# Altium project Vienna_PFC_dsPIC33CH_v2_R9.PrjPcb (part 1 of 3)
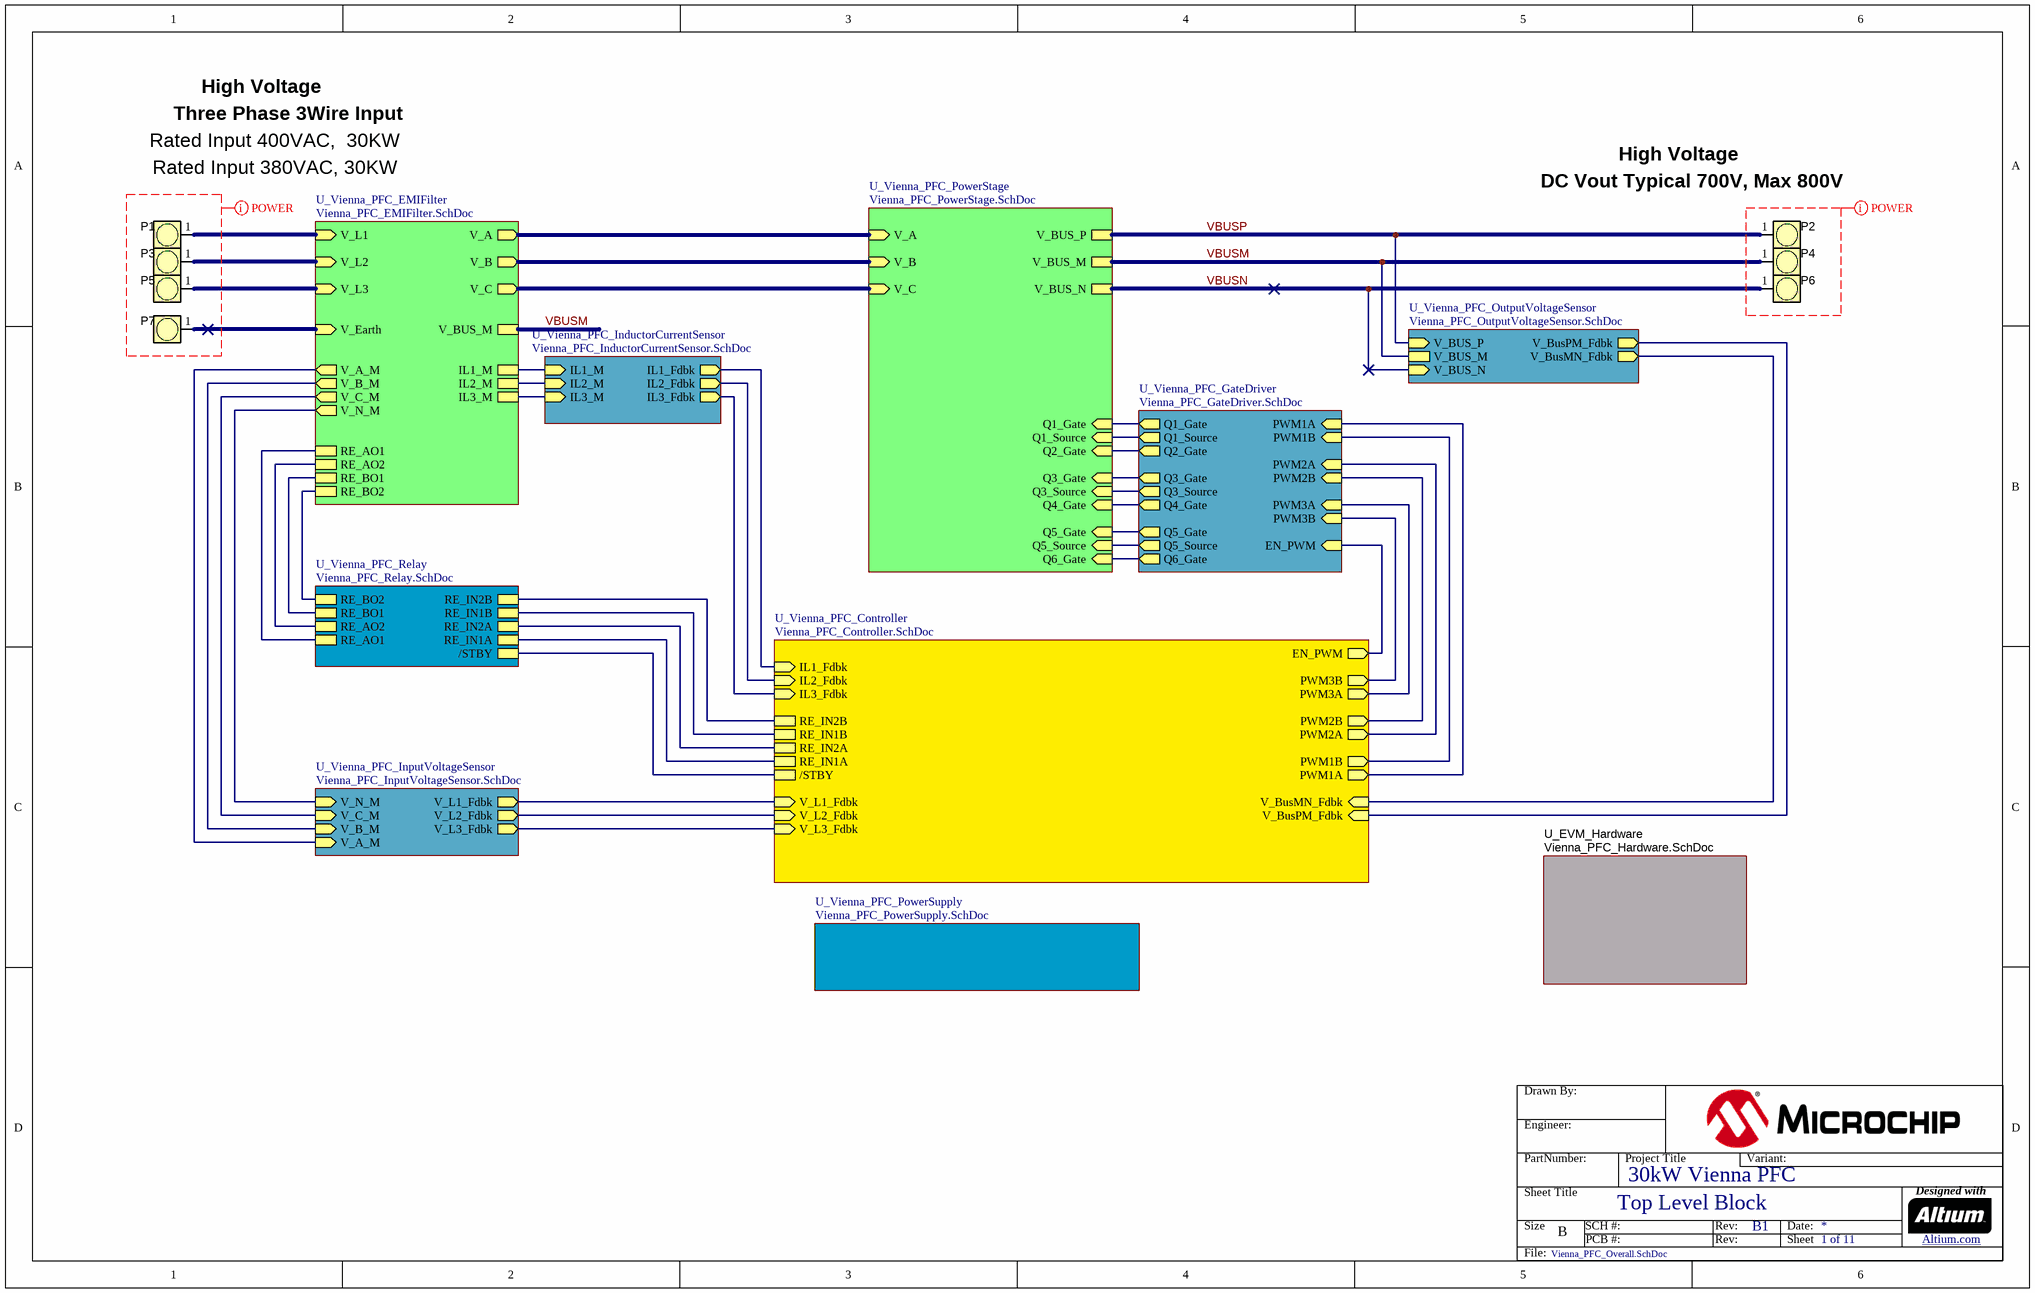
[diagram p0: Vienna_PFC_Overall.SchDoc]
11 sheets, 641 parts. Net scope: hierarchical (ports join the sheet entries above them; power ports are global).
Board file: Vienna_PFC_PCB.PcbDoc
Sheets:
  Vienna_PFC_Overall.SchDoc
    U_EVM_Hardware = Vienna_PFC_Hardware.SchDoc
    U_Vienna_PFC_InputVoltageSensor = Vienna_PFC_InputVoltageSensor.SchDoc
    U_Vienna_PFC_PowerStage = Vienna_PFC_PowerStage.SchDoc
    U_Vienna_PFC_GateDriver = Vienna_PFC_GateDriver.SchDoc
    U_Vienna_PFC_OutputVoltageSensor = Vienna_PFC_OutputVoltageSensor.SchDoc
    U_Vienna_PFC_InductorCurrentSensor = Vienna_PFC_InductorCurrentSensor.SchDoc
    U_Vienna_PFC_PowerSupply = Vienna_PFC_PowerSupply.SchDoc
    U_Vienna_PFC_EMIFilter = Vienna_PFC_EMIFilter.SchDoc
    U_Vienna_PFC_Relay = Vienna_PFC_Relay.SchDoc
    U_Vienna_PFC_Controller = Vienna_PFC_Controller.SchDoc

## Sheet Vienna_PFC_Overall.SchDoc
size B; DocumentNumber: 1; SheetNumber: 1; SheetTotal: 11

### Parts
(Parts that share a designator on the sheet are numbered #1, #2 ... from top to bottom, then left to right.)
?#1  (no value)  (graphical)
P1  Bush_7460408  [Bush7460408]  (value not drawn)
P2  Bush_7460408  [Bush7460408]  (value not drawn)
P3  Bush_7460408  [Bush7460408]  (value not drawn)
P4  Bush_7460408  [Bush7460408]  (value not drawn)
P5  Bush_7460408  [Bush7460408]  (value not drawn)
P6  Bush_7460408  [Bush7460408]  (value not drawn)
P7  Bush_7460408  [Bush7460408]  (value not drawn)

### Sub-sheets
U_EVM_Hardware = Vienna_PFC_Hardware.SchDoc: no entries
U_Vienna_PFC_Controller = Vienna_PFC_Controller.SchDoc: V_L3_Fdbk (in), PWM2A (out), PWM2B (out), IL1_Fdbk (in), IL2_Fdbk (in), IL3_Fdbk (in), V_L1_Fdbk (in), V_L2_Fdbk (in), V_BusPM_Fdbk (in), V_BusMN_Fdbk (in), EN_PWM (out), PWM3B (out), PWM1B (out), PWM3A (out), PWM1A (out), RE_IN2A, RE_IN1A, RE_IN2B, RE_IN1B, /STBY
U_Vienna_PFC_EMIFilter = Vienna_PFC_EMIFilter.SchDoc: RE_AO2, RE_BO2, V_L1 (in), V_L2 (in), V_L3 (in), V_Earth (in), V_A_M (out), V_B_M (out), V_C_M (out), V_BUS_M, V_N_M (out), IL1_M, IL2_M, IL3_M, V_A (out), V_C (out), V_B (out), RE_AO1, RE_BO1
U_Vienna_PFC_GateDriver = Vienna_PFC_GateDriver.SchDoc: PWM1A (in), PWM1B (in), PWM2A (in), PWM2B (in), PWM3A (in), PWM3B (in), Q1_Source (out), Q3_Source (out), Q5_Source (out), EN_PWM (in), Q1_Gate (out), Q3_Gate (out), Q5_Gate (out), Q2_Gate (out), Q4_Gate (out), Q6_Gate (out)
U_Vienna_PFC_InductorCurrentSensor = Vienna_PFC_InductorCurrentSensor.SchDoc: IL1_M (in), IL2_M (in), IL3_M (in), IL1_Fdbk (out), IL2_Fdbk (out), IL3_Fdbk (out)
U_Vienna_PFC_InputVoltageSensor = Vienna_PFC_InputVoltageSensor.SchDoc: V_A_M (in), V_B_M (in), V_C_M (in), V_N_M (in), V_L1_Fdbk (out), V_L2_Fdbk (out), V_L3_Fdbk (out)
U_Vienna_PFC_OutputVoltageSensor = Vienna_PFC_OutputVoltageSensor.SchDoc: V_BUS_P (in), V_BUS_N (in), V_BusPM_Fdbk (out), V_BusMN_Fdbk (out), V_BUS_M
U_Vienna_PFC_PowerStage = Vienna_PFC_PowerStage.SchDoc: V_A (in), V_B (in), V_C (in), Q1_Source (in), Q2_Gate (in), Q3_Source (in), Q5_Source (in), Q3_Gate (in), Q4_Gate (in), Q6_Gate (in), Q5_Gate (in), Q1_Gate (in), V_BUS_P, V_BUS_M, V_BUS_N
U_Vienna_PFC_PowerSupply = Vienna_PFC_PowerSupply.SchDoc: no entries
U_Vienna_PFC_Relay = Vienna_PFC_Relay.SchDoc: RE_AO1, RE_AO2, RE_BO1, RE_BO2, RE_IN2A, RE_IN1A, RE_IN2B, RE_IN1B, /STBY

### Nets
GND1: sheet U_Vienna_PFC_PowerStage/Q1_Source, sheet U_Vienna_PFC_GateDriver/Q1_Source
GND3: sheet U_Vienna_PFC_PowerStage/Q3_Source, sheet U_Vienna_PFC_GateDriver/Q3_Source
GND5: sheet U_Vienna_PFC_PowerStage/Q5_Source, sheet U_Vienna_PFC_GateDriver/Q5_Source
PE: P7.1 ; sheet U_Vienna_PFC_EMIFilter/V_Earth
EN_PWM: sheet U_Vienna_PFC_GateDriver/EN_PWM, sheet U_Vienna_PFC_Controller/EN_PWM
V_N_Meas: sheet U_Vienna_PFC_InputVoltageSensor/V_N_M, sheet U_Vienna_PFC_EMIFilter/V_N_M
VBUSM: P4.1 ; sheet U_Vienna_PFC_PowerStage/V_BUS_M, sheet U_Vienna_PFC_OutputVoltageSensor/V_BUS_M, sheet U_Vienna_PFC_EMIFilter/V_BUS_M  [project net V_BUS_M]
VBUSN: P6.1 ; sheet U_Vienna_PFC_PowerStage/V_BUS_N, sheet U_Vienna_PFC_OutputVoltageSensor/V_BUS_N
VBUSP: P2.1 ; sheet U_Vienna_PFC_PowerStage/V_BUS_P, sheet U_Vienna_PFC_OutputVoltageSensor/V_BUS_P
NetC14_2: sheet U_Vienna_PFC_InputVoltageSensor/V_C_M, sheet U_Vienna_PFC_EMIFilter/V_C_M
NetC15_2: sheet U_Vienna_PFC_InputVoltageSensor/V_B_M, sheet U_Vienna_PFC_EMIFilter/V_B_M
NetC16_2: sheet U_Vienna_PFC_InputVoltageSensor/V_A_M, sheet U_Vienna_PFC_EMIFilter/V_A_M
NetC110_1: sheet U_Vienna_PFC_InductorCurrentSensor/IL1_Fdbk, sheet U_Vienna_PFC_Controller/IL1_Fdbk
NetC112_1: sheet U_Vienna_PFC_InductorCurrentSensor/IL2_Fdbk, sheet U_Vienna_PFC_Controller/IL2_Fdbk
NetC114_1: sheet U_Vienna_PFC_InductorCurrentSensor/IL3_Fdbk, sheet U_Vienna_PFC_Controller/IL3_Fdbk
NetC122_2: sheet U_Vienna_PFC_InputVoltageSensor/V_L1_Fdbk, sheet U_Vienna_PFC_Controller/V_L1_Fdbk
NetC139_2: sheet U_Vienna_PFC_InputVoltageSensor/V_L2_Fdbk, sheet U_Vienna_PFC_Controller/V_L2_Fdbk
NetC149_2: sheet U_Vienna_PFC_InputVoltageSensor/V_L3_Fdbk, sheet U_Vienna_PFC_Controller/V_L3_Fdbk
NetC159_2: sheet U_Vienna_PFC_OutputVoltageSensor/V_BusPM_Fdbk, sheet U_Vienna_PFC_Controller/V_BusPM_Fdbk
NetC168_2: sheet U_Vienna_PFC_OutputVoltageSensor/V_BusMN_Fdbk, sheet U_Vienna_PFC_Controller/V_BusMN_Fdbk
NetJ5_13: sheet U_Vienna_PFC_Relay/RE_IN1B, sheet U_Vienna_PFC_Controller/RE_IN1B
NetJ5_15: sheet U_Vienna_PFC_Relay/RE_IN2B, sheet U_Vienna_PFC_Controller/RE_IN2B
NetJ5_31: sheet U_Vienna_PFC_Relay//STBY, sheet U_Vienna_PFC_Controller//STBY
NetJ5_33: sheet U_Vienna_PFC_Relay/RE_IN1A, sheet U_Vienna_PFC_Controller/RE_IN1A
NetJ5_35: sheet U_Vienna_PFC_Relay/RE_IN2A, sheet U_Vienna_PFC_Controller/RE_IN2A
NetJ5_37: sheet U_Vienna_PFC_GateDriver/PWM3A, sheet U_Vienna_PFC_Controller/PWM3A
NetJ5_40: sheet U_Vienna_PFC_GateDriver/PWM2B, sheet U_Vienna_PFC_Controller/PWM2B
NetJ5_41: sheet U_Vienna_PFC_GateDriver/PWM3B, sheet U_Vienna_PFC_Controller/PWM3B
NetJ5_42: sheet U_Vienna_PFC_GateDriver/PWM2A, sheet U_Vienna_PFC_Controller/PWM2A
NetJ5_45: sheet U_Vienna_PFC_GateDriver/PWM1A, sheet U_Vienna_PFC_Controller/PWM1A
NetJ5_47: sheet U_Vienna_PFC_GateDriver/PWM1B, sheet U_Vienna_PFC_Controller/PWM1B
NetLboost1_1: sheet U_Vienna_PFC_PowerStage/V_A, sheet U_Vienna_PFC_EMIFilter/V_A
NetLboost2_1: sheet U_Vienna_PFC_PowerStage/V_B, sheet U_Vienna_PFC_EMIFilter/V_B
NetLboost3_1: sheet U_Vienna_PFC_PowerStage/V_C, sheet U_Vienna_PFC_EMIFilter/V_C
NetP1_1: P1.1 ; sheet U_Vienna_PFC_EMIFilter/V_L1
NetP3_1: P3.1 ; sheet U_Vienna_PFC_EMIFilter/V_L2
NetP5_1: P5.1 ; sheet U_Vienna_PFC_EMIFilter/V_L3
NetR11_2: sheet U_Vienna_PFC_PowerStage/Q2_Gate, sheet U_Vienna_PFC_GateDriver/Q2_Gate
NetR12_2: sheet U_Vienna_PFC_PowerStage/Q1_Gate, sheet U_Vienna_PFC_GateDriver/Q1_Gate
NetR28_2: sheet U_Vienna_PFC_PowerStage/Q4_Gate, sheet U_Vienna_PFC_GateDriver/Q4_Gate
NetR29_2: sheet U_Vienna_PFC_PowerStage/Q3_Gate, sheet U_Vienna_PFC_GateDriver/Q3_Gate
NetR44_2: sheet U_Vienna_PFC_PowerStage/Q6_Gate, sheet U_Vienna_PFC_GateDriver/Q6_Gate
NetR45_2: sheet U_Vienna_PFC_PowerStage/Q5_Gate, sheet U_Vienna_PFC_GateDriver/Q5_Gate
NetR171_2: sheet U_Vienna_PFC_InductorCurrentSensor/IL1_M, sheet U_Vienna_PFC_EMIFilter/IL1_M
NetR174_2: sheet U_Vienna_PFC_InductorCurrentSensor/IL2_M, sheet U_Vienna_PFC_EMIFilter/IL2_M
NetR177_2: sheet U_Vienna_PFC_InductorCurrentSensor/IL3_M, sheet U_Vienna_PFC_EMIFilter/IL3_M
NetR180_2: sheet U_Vienna_PFC_EMIFilter/RE_AO1, sheet U_Vienna_PFC_Relay/RE_AO1
NetR181_2: sheet U_Vienna_PFC_EMIFilter/RE_AO2, sheet U_Vienna_PFC_Relay/RE_AO2
NetR182_2: sheet U_Vienna_PFC_EMIFilter/RE_BO1, sheet U_Vienna_PFC_Relay/RE_BO1
NetR183_2: sheet U_Vienna_PFC_EMIFilter/RE_BO2, sheet U_Vienna_PFC_Relay/RE_BO2

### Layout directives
net class POWER: (no net found under the mark)

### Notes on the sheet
- High Voltage
- Rated Input 400VAC,  30KW
- Rated Input 380VAC, 30KW
- Three Phase 3Wire Input
- (near P2) DC Vout Typical 700V, Max 800V
- Top Level Block
- 30kW Vienna PFC
- B1

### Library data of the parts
?#1 = Title Block B
P1-P7 = Bush_7460408: TERM PWR ELEMENT M5 12 PIN PCB; Manufacturer: Wurth Electronics Inc.

## Sheet Vienna_PFC_Hardware.SchDoc: EVM Hardware
size B; Date: Not shown in title block; ApprovedBy: Not shown in title block; CheckedBy: Not shown in title block; Author: Not shown in title block; CompanyName: Not shown in title block; DrawnBy: SJC; Engineer: SJC; Organization: Not shown in title block; Address1: Not shown in title block; Address2: Not shown in title block; Address3: Not shown in title block; Address4: Not shown in title block; DocumentNumber: 11; Revision: B1; SheetNumber: 11; SheetTotal: 11; PageSetup: Record=PageOptions¦CenterHorizontal=True¦CenterVertical=True¦PrintScale=1.00¦XCorrection=1.00¦YCorrection=1.00¦PrintKind=0¦BorderSize=5000000¦LeftOffset=0¦BottomOffset=0¦Orientation=2¦PaperLength=1000¦PaperWidth=1000¦Scale=100¦PaperSource=15¦PrintQuality=600¦MediaType=1¦DitherType=10¦PaperKind=Letter¦PrintScaleMode=1; SheetTitle: **
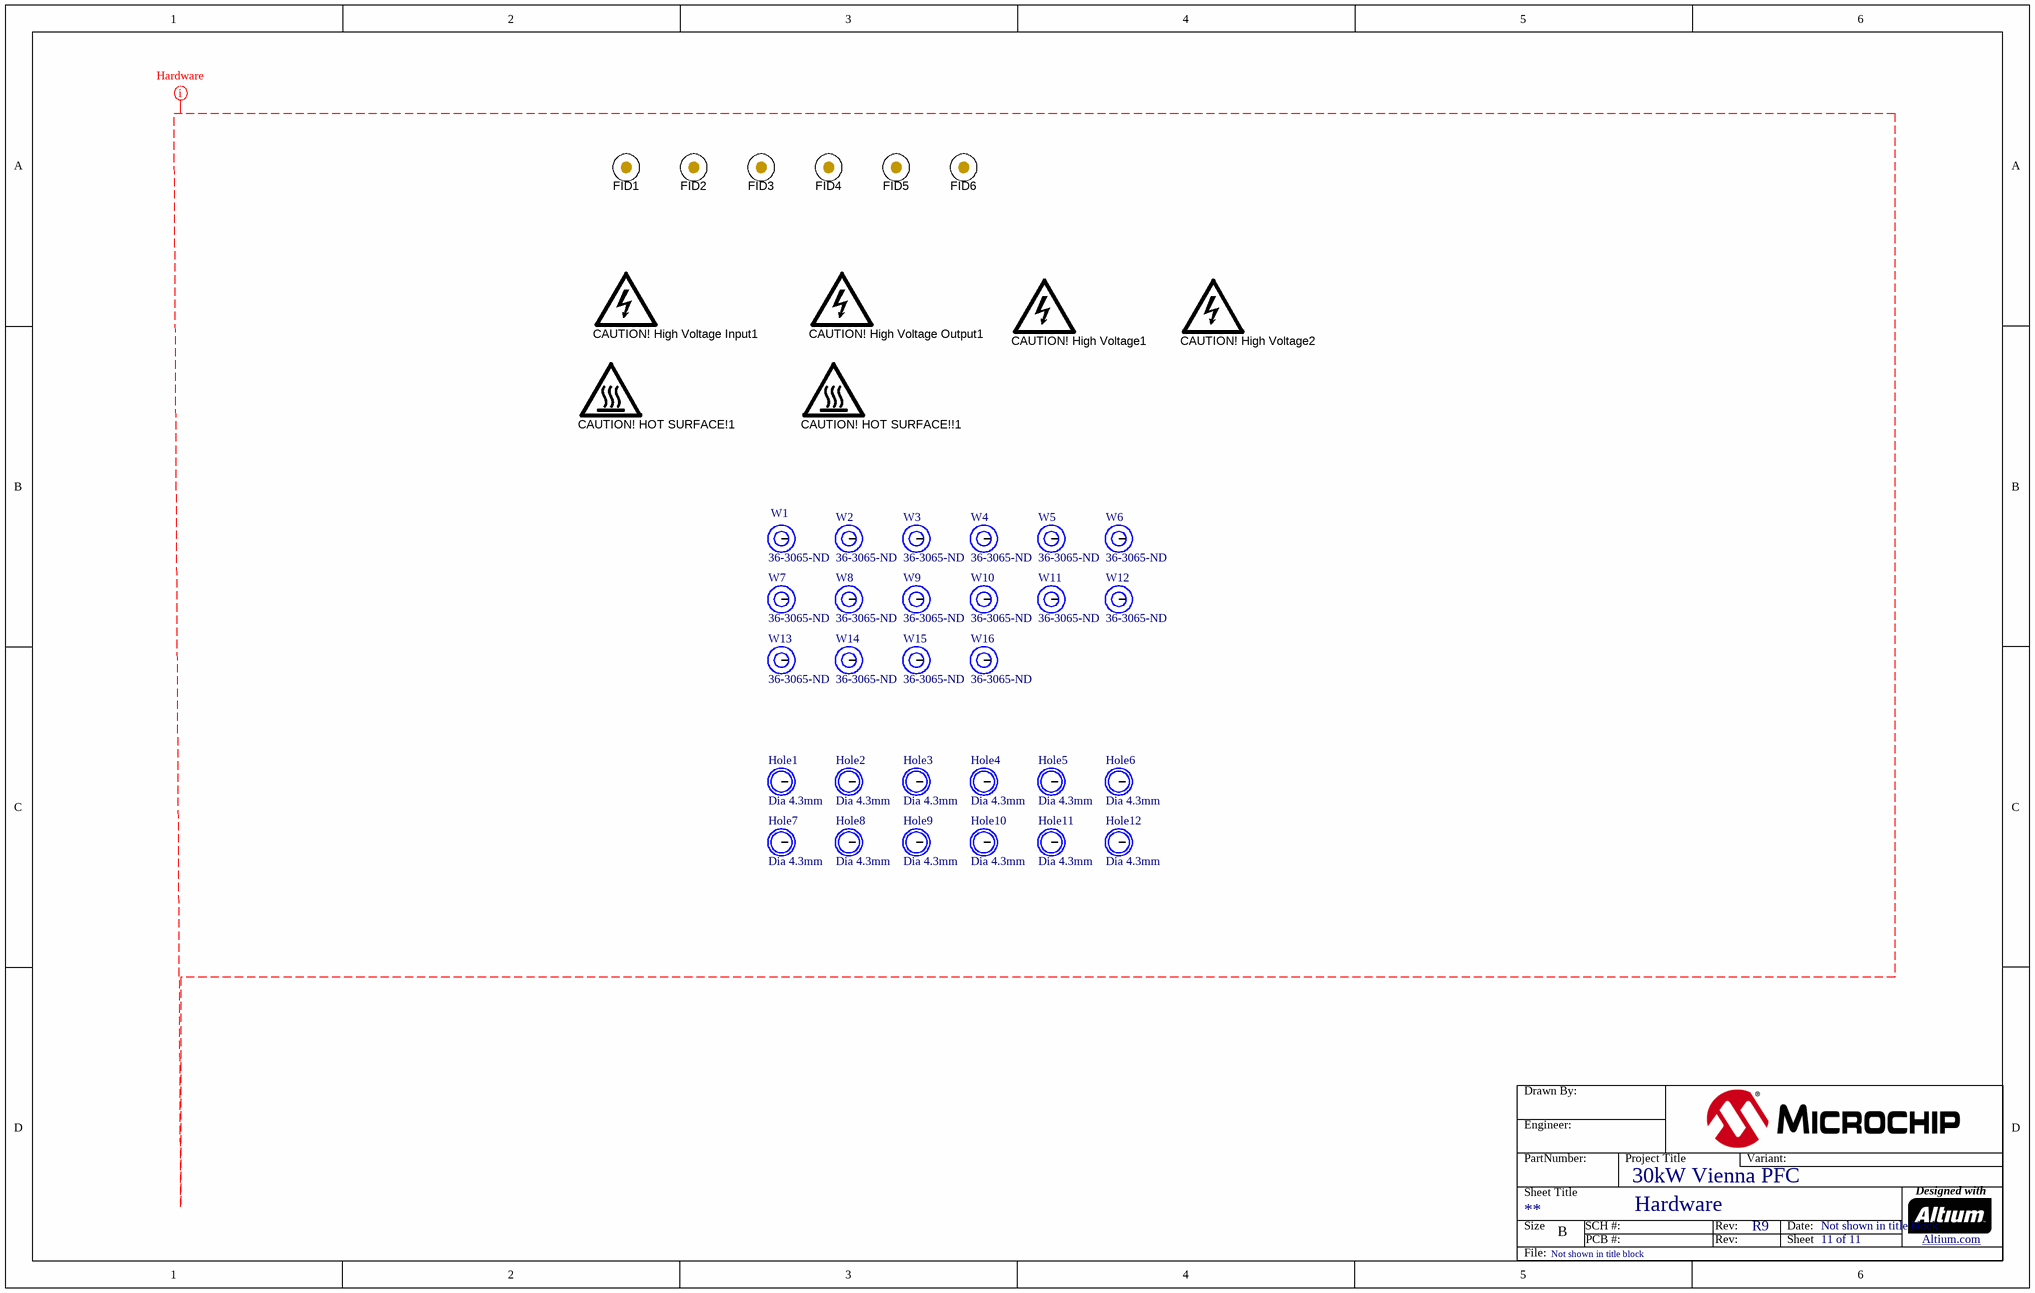
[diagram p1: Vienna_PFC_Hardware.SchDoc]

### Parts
(Parts that share a designator on the sheet are numbered #1, #2 ... from top to bottom, then left to right.)
?#2  (no value)  (graphical)
CAUTION!_High_Voltage1  DANGER HIGH VOLTAGE  [IEC_HighVoltage_Small]  (value not drawn)  (no BOM)
CAUTION!_High_Voltage2  DANGER HIGH VOLTAGE  [IEC_HighVoltage_Small]  (value not drawn)  (no BOM)
CAUTION!_High_Voltage_Input1  DANGER HIGH VOLTAGE  [IEC_HighVoltage_Small]  (value not drawn)  (no BOM)
CAUTION!_High_Voltage_Output1  DANGER HIGH VOLTAGE  [IEC_HighVoltage_Small]  (value not drawn)  (no BOM)
CAUTION!_HOT_SURFACE!1  CAUTION HOT SURFACE  [IEC_HotSurface_Small]  (value not drawn)  (no BOM)
CAUTION!_HOT_SURFACE!!1  CAUTION HOT SURFACE  [IEC_HotSurface_Small]  (value not drawn)  (no BOM)
FID1  Fiducial  [Fiducial10-20]  (value not drawn)  (no BOM)
FID2  Fiducial  [Fiducial10-20]  (value not drawn)
FID3  Fiducial  [Fiducial10-20]  (value not drawn)
FID4  Fiducial  [Fiducial10-20]  (value not drawn)  (no BOM)
FID5  Fiducial  [Fiducial10-20]  (value not drawn)
FID6  Fiducial  [Fiducial10-20]  (value not drawn)
Hole1  Dia 4.3mm  [Hole-Dia 4.3mm]
Hole2  Dia 4.3mm  [Hole-Dia 4.3mm]
Hole3  Dia 4.3mm  [Hole-Dia 4.3mm]
Hole4  Dia 4.3mm  [Hole-Dia 4.3mm]
Hole5  Dia 4.3mm  [Hole-Dia 4.3mm]
Hole6  Dia 4.3mm  [Hole-Dia 4.3mm]
Hole7  Dia 4.3mm  [Hole-Dia 4.3mm]
Hole8  Dia 4.3mm  [Hole-Dia 4.3mm]
Hole9  Dia 4.3mm  [Hole-Dia 4.3mm]
Hole10  Dia 4.3mm  [Hole-Dia 4.3mm]
Hole11  Dia 4.3mm  [Hole-Dia 4.3mm]
Hole12  Dia 4.3mm  [Hole-Dia 4.3mm]
W1  36-3065-ND  [WASHER SHOULDER]
W2  36-3065-ND  [WASHER SHOULDER]
W3  36-3065-ND  [WASHER SHOULDER]
W4  36-3065-ND  [WASHER SHOULDER]
W5  36-3065-ND  [WASHER SHOULDER]
W6  36-3065-ND  [WASHER SHOULDER]
W7  36-3065-ND  [WASHER SHOULDER]
W8  36-3065-ND  [WASHER SHOULDER]
W9  36-3065-ND  [WASHER SHOULDER]
W10  36-3065-ND  [WASHER SHOULDER]
W11  36-3065-ND  [WASHER SHOULDER]
W12  36-3065-ND  [WASHER SHOULDER]
W13  36-3065-ND  [WASHER SHOULDER]
W14  36-3065-ND  [WASHER SHOULDER]
W15  36-3065-ND  [WASHER SHOULDER]
W16  36-3065-ND  [WASHER SHOULDER]

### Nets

Not connected (* = marked no-connect by the designer): Hole1 0; Hole2 0; Hole3 0; Hole4 0; Hole5 0; Hole6 0; Hole7 0; Hole8 0; Hole9 0; Hole10 0; Hole11 0; Hole12 0; W1 0; W2 0; W3 0; W4 0; W5 0; W6 0; W7 0; W8 0; W9 0; W10 0; W11 0; W12 0; W13 0; W14 0; W15 0; W16 0

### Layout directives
net class Hardware: (no net found under the mark)

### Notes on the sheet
- 30kW Vienna PFC
- Hardware
- R9

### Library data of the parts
?#2 = Title Block B
CAUTION!_High_Voltage1 CAUTION!_High_Voltage2 CAUTION!_High_Voltage_Input1 CAUTION!_High_Voltage_Output1 = IEC_HighVoltage: IEC 61010-1 High Voltage Warning; SymbolCreator: a0412235
CAUTION!_HOT_SURFACE!1 CAUTION!_HOT_SURFACE!!1 = IEC_HotSurface: IEC 61010-1 Hot Surface Warning; SymbolCreator: a0412235
FID1-FID6 = Fiducial: Fiducial mark.  There is nothing to buy or mount.; SymbolCreator: codlsc
Hole1-Hole12 = Hole: Hole  Dia 4.3mm
W1-W16 = WASHER SHOULDER - 3065: WASHER SHOULDER #8 FIBRE

## Sheet Vienna_PFC_InputVoltageSensor.SchDoc
size C; DocumentNumber: 6; SheetNumber: 6; SheetTotal: 11
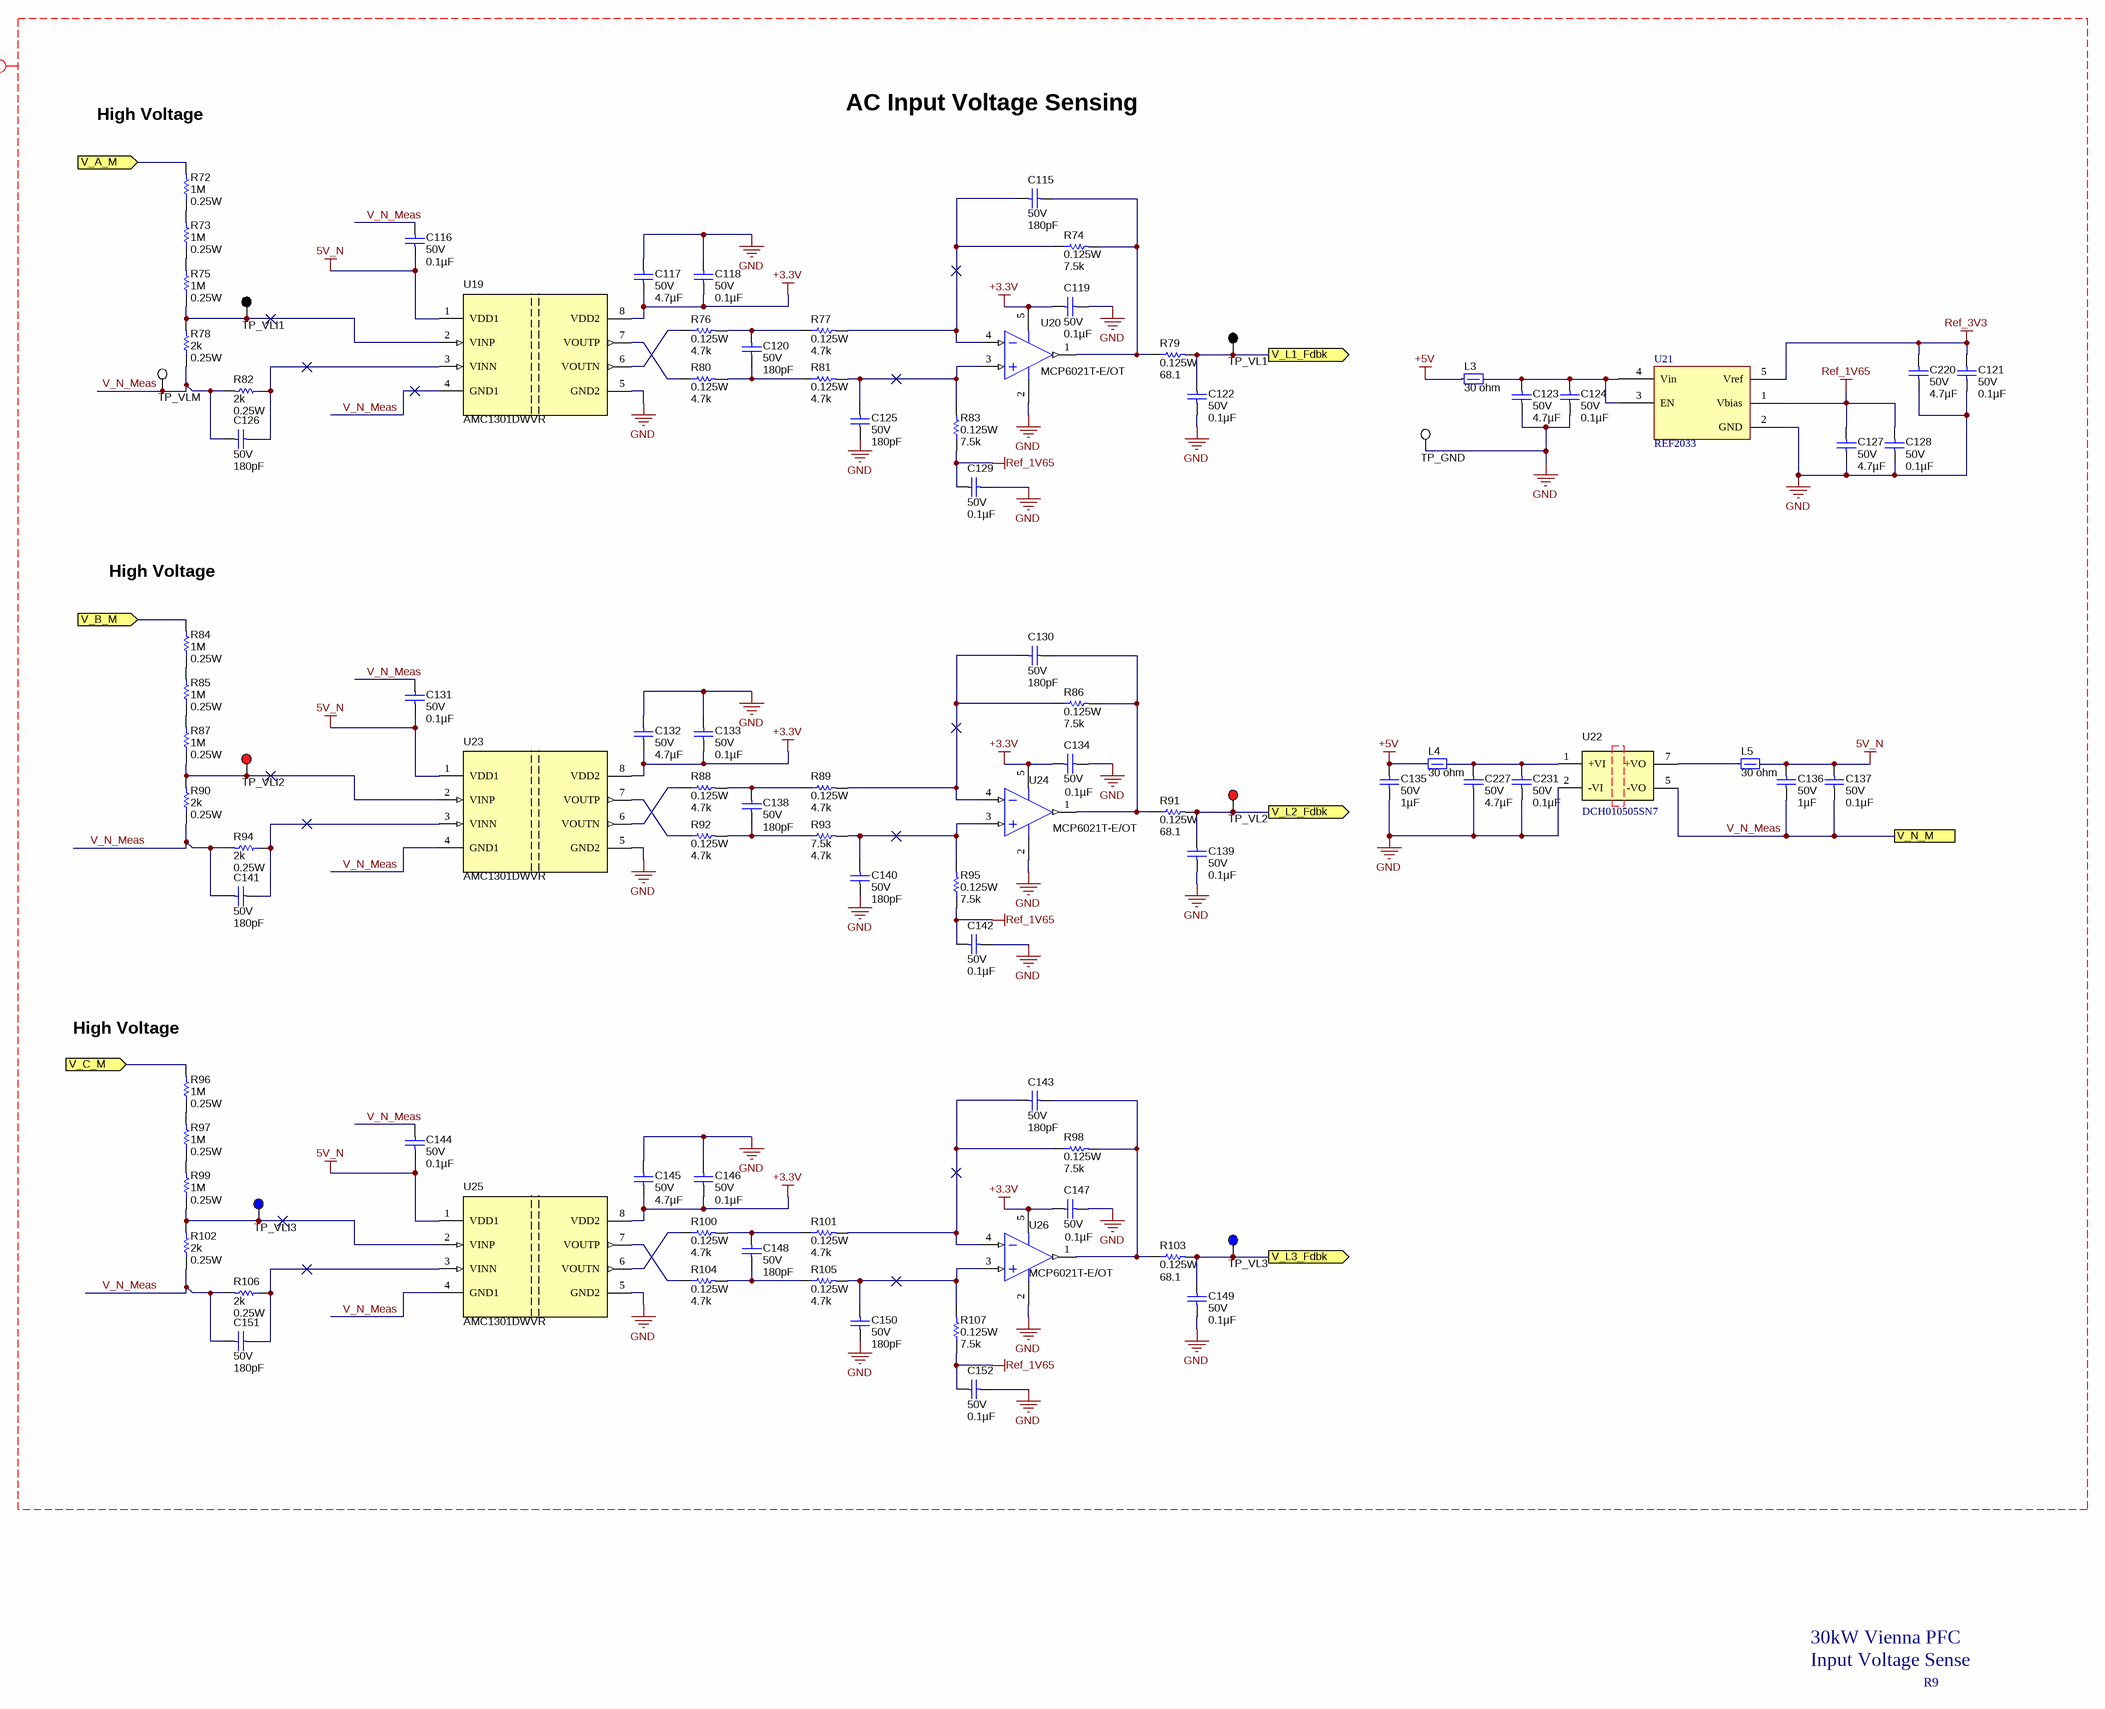
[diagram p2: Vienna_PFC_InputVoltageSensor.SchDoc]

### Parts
(Parts that share a designator on the sheet are numbered #1, #2 ... from top to bottom, then left to right.)
?#3  (no value)  (graphical)
C115  VDC_V: 50V  ValueDisplayed: 180pF  [0805_HV]  (hidden comment: C0805C181J5GACTU)
C116  VDC_V: 50V  ValueDisplayed: 0.1µF  [0805_HV]  (hidden comment: C0805C104J5RACTU)
C117  VDC_V: 50V  ValueDisplayed: 4.7µF  [0805_HV]  (hidden comment: C2012X5R1H475K125AB)
C118  VDC_V: 50V  ValueDisplayed: 0.1µF  [0805_HV]  (hidden comment: C0805C104J5RACTU)
C119  VDC_V: 50V  ValueDisplayed: 0.1µF  [0805_HV]  (hidden comment: C0805C104J5RACTU)
C120  VDC_V: 50V  ValueDisplayed: 180pF  [0805_HV]  (hidden comment: C0805C181J5GACTU)
C121  VDC_V: 50V  ValueDisplayed: 0.1µF  [0805_HV]  (hidden comment: C0805C104J5RACTU)
C122  VDC_V: 50V  ValueDisplayed: 0.1µF  [0805_HV]  (hidden comment: C0805C104J5RACTU)
C123  VDC_V: 50V  ValueDisplayed: 4.7µF  [0805_HV]  (hidden comment: C2012X5R1H475K125AB)
C124  VDC_V: 50V  ValueDisplayed: 0.1µF  [0805_HV]  (hidden comment: C0805C104J5RACTU)
C125  VDC_V: 50V  ValueDisplayed: 180pF  [0805_HV]  (hidden comment: C0805C181J5GACTU)
C126  VDC_V: 50V  ValueDisplayed: 180pF  [0805_HV]  (hidden comment: C0805C181J5GACTU)
C127  VDC_V: 50V  ValueDisplayed: 4.7µF  [0805_HV]  (hidden comment: C2012X5R1H475K125AB)
C128  VDC_V: 50V  ValueDisplayed: 0.1µF  [0805_HV]  (hidden comment: C0805C104J5RACTU)
C129  VDC_V: 50V  ValueDisplayed: 0.1µF  [0805_HV]  (hidden comment: C0805C104J5RACTU)
C130  VDC_V: 50V  ValueDisplayed: 180pF  [0805_HV]  (hidden comment: C0805C181J5GACTU)
C131  VDC_V: 50V  ValueDisplayed: 0.1µF  [0805_HV]  (hidden comment: C0805C104J5RACTU)
C132  VDC_V: 50V  ValueDisplayed: 4.7µF  [0805_HV]  (hidden comment: C2012X5R1H475K125AB)
C133  VDC_V: 50V  ValueDisplayed: 0.1µF  [0805_HV]  (hidden comment: C0805C104J5RACTU)
C134  VDC_V: 50V  ValueDisplayed: 0.1µF  [0805_HV]  (hidden comment: C0805C104J5RACTU)
C135  VDC_V: 50V  ValueDisplayed: 1µF  [0805_HV]  (hidden comment: C0805C105K5RACTU)
C136  VDC_V: 50V  ValueDisplayed: 1µF  [0805_HV]  (hidden comment: C0805C105K5RACTU)
C137  VDC_V: 50V  ValueDisplayed: 0.1µF  [0805_HV]  (hidden comment: C0805C104J5RACTU)
C138  VDC_V: 50V  ValueDisplayed: 180pF  [0805_HV]  (hidden comment: C0805C181J5GACTU)
C139  VDC_V: 50V  ValueDisplayed: 0.1µF  [0805_HV]  (hidden comment: C0805C104J5RACTU)
C140  VDC_V: 50V  ValueDisplayed: 180pF  [0805_HV]  (hidden comment: C0805C181J5GACTU)
C141  VDC_V: 50V  ValueDisplayed: 180pF  [0805_HV]  (hidden comment: C0805C181J5GACTU)
C142  VDC_V: 50V  ValueDisplayed: 0.1µF  [0805_HV]  (hidden comment: C0805C104J5RACTU)
C143  VDC_V: 50V  ValueDisplayed: 180pF  [0805_HV]  (hidden comment: C0805C181J5GACTU)
C144  VDC_V: 50V  ValueDisplayed: 0.1µF  [0805_HV]  (hidden comment: C0805C104J5RACTU)
C145  VDC_V: 50V  ValueDisplayed: 4.7µF  [0805_HV]  (hidden comment: C2012X5R1H475K125AB)
C146  VDC_V: 50V  ValueDisplayed: 0.1µF  [0805_HV]  (hidden comment: C0805C104J5RACTU)
C147  VDC_V: 50V  ValueDisplayed: 0.1µF  [0805_HV]  (hidden comment: C0805C104J5RACTU)
C148  VDC_V: 50V  ValueDisplayed: 180pF  [0805_HV]  (hidden comment: C0805C181J5GACTU)
C149  VDC_V: 50V  ValueDisplayed: 0.1µF  [0805_HV]  (hidden comment: C0805C104J5RACTU)
C150  VDC_V: 50V  ValueDisplayed: 180pF  [0805_HV]  (hidden comment: C0805C181J5GACTU)
C151  VDC_V: 50V  ValueDisplayed: 180pF  [0805_HV]  (hidden comment: C0805C181J5GACTU)
C152  VDC_V: 50V  ValueDisplayed: 0.1µF  [0805_HV]  (hidden comment: C0805C104J5RACTU)
C220  VDC_V: 50V  ValueDisplayed: 4.7µF  [0805_HV]  (hidden comment: C2012X5R1H475K125AB)
C227  VDC_V: 50V  ValueDisplayed: 4.7µF  [0805_HV]  (hidden comment: C2012X5R1H475K125AB)
C231  VDC_V: 50V  ValueDisplayed: 0.1µF  [0805_HV]  (hidden comment: C0805C104J5RACTU)
L3  value 30 ohm  [0805_HV]  (hidden comment: MPZ2012S300AT000)
L4  value 30 ohm  [0805_HV]  (hidden comment: MPZ2012S300AT000)
L5  value 30 ohm  [0805_HV]  (hidden comment: MPZ2012S300AT000)
R72  value 1M  Power_W: 0.25W  [1206_190]  (hidden comment: TNPW12061M00BXTY)
R73  value 1M  Power_W: 0.25W  [1206_190]  (hidden comment: TNPW12061M00BXTY)
R74  Value2: 0.125W  ValueDisplayed: 7.5k  [0805_HV]  (hidden comment: CRCW08057K50FKEA)
R75  value 1M  Power_W: 0.25W  [1206_190]  (hidden comment: TNPW12061M00BXTY)
R76  Value2: 0.125W  ValueDisplayed: 4.7k  [0805_HV]  (hidden comment: CRCW08054K70FKEA)
R77  Value2: 0.125W  ValueDisplayed: 4.7k  [0805_HV]  (hidden comment: CRCW08054K70FKEA)
R78  value 2k  Power_W: 0.25W  [1206_190]  (hidden comment: TNPW12062K00BEEA)
R79  Value2: 0.125W  ValueDisplayed: 68.1  [0805_HV]  (hidden comment: CRCW080568R1FKEA)
R80  Value2: 0.125W  ValueDisplayed: 4.7k  [0805_HV]  (hidden comment: CRCW08054K70FKEA)
R81  Value2: 0.125W  ValueDisplayed: 4.7k  [0805_HV]  (hidden comment: CRCW08054K70FKEA)
R82  value 2k  Power_W: 0.25W  [1206_190]  (hidden comment: TNPW12062K00BEEA)
R83  Value2: 0.125W  ValueDisplayed: 7.5k  [0805_HV]  (hidden comment: CRCW08057K50FKEA)
R84  value 1M  Power_W: 0.25W  [1206_190]  (hidden comment: TNPW12061M00BXTY)
R85  value 1M  Power_W: 0.25W  [1206_190]  (hidden comment: TNPW12061M00BXTY)
R86  Value2: 0.125W  ValueDisplayed: 7.5k  [0805_HV]  (hidden comment: CRCW08057K50FKEA)
R87  value 1M  Power_W: 0.25W  [1206_190]  (hidden comment: TNPW12061M00BXTY)
R88  Value2: 0.125W  ValueDisplayed: 4.7k  [0805_HV]  (hidden comment: CRCW08054K70FKEA)
R89  Value2: 0.125W  ValueDisplayed: 4.7k  [0805_HV]  (hidden comment: CRCW08054K70FKEA)
R90  value 2k  Power_W: 0.25W  [1206_190]  (hidden comment: TNPW12062K00BEEA)
R91  Value2: 0.125W  ValueDisplayed: 68.1  [0805_HV]  (hidden comment: CRCW080568R1FKEA)
R92  Value2: 0.125W  ValueDisplayed: 4.7k  [0805_HV]  (hidden comment: CRCW08054K70FKEA)
R93  Value2: 7.5k  ValueDisplayed: 4.7k  [0805_HV]  (hidden comment: CRCW08054K70FKEA)
R94  value 2k  Power_W: 0.25W  [1206_190]  (hidden comment: TNPW12062K00BEEA)
R95  Value2: 0.125W  ValueDisplayed: 7.5k  [0805_HV]  (hidden comment: CRCW08057K50FKEA)
R96  value 1M  Power_W: 0.25W  [1206_190]  (hidden comment: TNPW12061M00BXTY)
R97  value 1M  Power_W: 0.25W  [1206_190]  (hidden comment: TNPW12061M00BXTY)
R98  Value2: 0.125W  ValueDisplayed: 7.5k  [0805_HV]  (hidden comment: CRCW08057K50FKEA)
R99  value 1M  Power_W: 0.25W  [1206_190]  (hidden comment: TNPW12061M00BXTY)
R100  Value2: 0.125W  ValueDisplayed: 4.7k  [0805_HV]  (hidden comment: CRCW08054K70FKEA)
R101  Value2: 0.125W  ValueDisplayed: 4.7k  [0805_HV]  (hidden comment: CRCW08054K70FKEA)
R102  value 2k  Power_W: 0.25W  [1206_190]  (hidden comment: TNPW12062K00BEEA)
R103  Value2: 0.125W  ValueDisplayed: 68.1  [0805_HV]  (hidden comment: CRCW080568R1FKEA)
R104  Value2: 0.125W  ValueDisplayed: 4.7k  [0805_HV]  (hidden comment: CRCW08054K70FKEA)
R105  Value2: 0.125W  ValueDisplayed: 4.7k  [0805_HV]  (hidden comment: CRCW08054K70FKEA)
R106  value 2k  Power_W: 0.25W  [1206_190]  (hidden comment: TNPW12062K00BEEA)
R107  Value2: 0.125W  ValueDisplayed: 7.5k  [0805_HV]  (hidden comment: CRCW08057K50FKEA)
TP_GND  5012  [Keystone5012]  (value not drawn)
TP_VL1  5011  [Keystone5011]  (value not drawn)
TP_VL2  5010  [Keystone5010]  (value not drawn)
TP_VL3  5127  [Keystone5127]  (value not drawn)
TP_VLI1  5011  [Keystone5011]  (value not drawn)
TP_VLI2  5010  [Keystone5010]  (value not drawn)
TP_VLI3  5127  [Keystone5127]  (value not drawn)
TP_VLM  5012  [Keystone5012]  (value not drawn)
U19  AMC1301DWVR  [AMC1301]
U20  MCP6021T-E/OT  [OPA320]
U21  REF2033  [REF2033]
U22  DCH010505SN7  [DCH010505SN7]
U23  AMC1301DWVR  [AMC1301]
U24  MCP6021T-E/OT  [OPA320]
U25  AMC1301DWVR  [AMC1301]
U26  MCP6021T-E/OT  [OPA320]

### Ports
V_A_M (in), V_B_M (in), V_C_M (in), V_L1_Fdbk (out), V_L2_Fdbk (out), V_L3_Fdbk (out), V_N_M

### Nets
5V_N: C116.2 C131.2 C136.1 C137.1 C144.2 L5.2 U19.1(VDD1) U23.1(VDD1) U25.1(VDD1)
+3.3V: C117.2 C118.2 C119.1 C132.2 C133.2 C134.1 C145.2 C146.2 C147.1 U19.8(VDD2) U20.5(V+) U23.8(VDD2) U24.5(V+) U25.8(VDD2) U26.5(V+)
+5V: C135.1 L3.1 L4.1
GND: C117.1 C118.1 C119.2 C121.2 C122.1 C123.2 C124.2 C125.2 C127.2 C128.2 C129.2 C132.1 C133.1 C134.2 C135.2 C139.1 C140.2 C142.2 C145.1 C146.1 C147.2 C149.1 C150.2 C152.2 C220.2 C227.2 C231.2 TP_GND.1 U19.5(GND2) U20.2(V-) U21.2(GND) U22.2(-VI) U23.5(GND2) U24.2(V-) U25.5(GND2) U26.2(V-)
Ref_1V65: C127.1 C128.1 C129.1 C142.1 C152.1 R83.1 R95.1 R107.1 U21.1(Vbias)
Ref_3V3: C121.1 C220.1 U21.5(Vref)
V_N_Meas: C116.1 C126.2 C131.1 C136.2 C137.2 C141.2 C144.1 C151.2 R78.1 R82.2 R90.1 R94.2 R102.1 R106.2 TP_VLM.1 U19.4(GND1) U22.5(-VO) U23.4(GND1) U25.4(GND1) ; port V_N_M
NetC14_2: R96.2 ; port V_C_M
NetC15_2: R84.2 ; port V_B_M
NetC16_2: R72.2 ; port V_A_M
NetC115_1: C115.1 R74.2 R79.1 U20.1(OUT)
NetC115_2: C115.2 R74.1 R77.2 U20.4(IN-)
NetC120_1: C120.1 R76.2 R77.1
NetC120_2: C120.2 R80.2 R81.1
NetC122_2: C122.2 R79.2 TP_VL1.1 ; port V_L1_Fdbk
NetC123_1: C123.1 C124.1 L3.2 U21.3(EN) U21.4(Vin)
NetC125_1: C125.1 R81.2 R83.2 U20.3(IN+)
NetC126_1: C126.1 R82.1 U19.3(VINN)
NetC130_1: C130.1 R86.2 R91.1 U24.1(OUT)
NetC130_2: C130.2 R86.1 R89.2 U24.4(IN-)
NetC138_1: C138.1 R88.2 R89.1
NetC138_2: C138.2 R92.2 R93.1
NetC139_2: C139.2 R91.2 TP_VL2.1 ; port V_L2_Fdbk
NetC140_1: C140.1 R93.2 R95.2 U24.3(IN+)
NetC141_1: C141.1 R94.1 U23.3(VINN)
NetC143_1: C143.1 R98.2 R103.1 U26.1(OUT)
NetC143_2: C143.2 R98.1 R101.2 U26.4(IN-)
NetC148_1: C148.1 R100.2 R101.1
NetC148_2: C148.2 R104.2 R105.1
NetC149_2: C149.2 R103.2 TP_VL3.1 ; port V_L3_Fdbk
NetC150_1: C150.1 R105.2 R107.2 U26.3(IN+)
NetC151_1: C151.1 R106.1 U25.3(VINN)
NetC227_1: C227.1 C231.1 L4.2 U22.1(+VI)
NetL5_1: L5.1 U22.7(+VO)
NetR72_1: R72.1 R73.2
NetR73_1: R73.1 R75.2
NetR75_1: R75.1 R78.2 TP_VLI1.1 U19.2(VINP)
NetR76_1: R76.1 U19.6(VOUTN)
NetR80_1: R80.1 U19.7(VOUTP)
NetR84_1: R84.1 R85.2
NetR85_1: R85.1 R87.2
NetR87_1: R87.1 R90.2 TP_VLI2.1 U23.2(VINP)
NetR88_1: R88.1 U23.6(VOUTN)
NetR92_1: R92.1 U23.7(VOUTP)
NetR96_1: R96.1 R97.2
NetR97_1: R97.1 R99.2
NetR99_1: R99.1 R102.2 TP_VLI3.1 U25.2(VINP)
NetR100_1: R100.1 U25.6(VOUTN)
NetR104_1: R104.1 U25.7(VOUTP)

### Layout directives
net class InputVoltage: 5V_N, +3.3V, +5V, GND, Ref_1V65, Ref_3V3, V_N_Meas

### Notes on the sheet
- High Voltage
- AC Input Voltage Sensing
- (near R96) High Voltage
- 30kW Vienna PFC
- Input Voltage Sense
- R9

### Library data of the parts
?#3 = Title Block C
C115 C120 C125 C126 C130 C138 C140 C141 C143 C148 C150 C151 = C0805C181J5GACTU: CAP, CERM, 180 pF, 50 V, +/- 5%, X7R, 0805; Manufacturer: Kemet; CompType: Capacitor; Tolerance_%: 5; TaMin_C: -55; TaMax_C: 125; Cap_Case: 0805; AEC Category: Q200
C116 C118 C119 C121 C122 C124 C128 C129 C131 C133 C134 C137 C139 C142 C144 C146 C147 C149 C152 C231 = C0805C104J5RACTU: CAP, CERM, 0.1 µF, 50 V, +/- 5%, X7R, 0805; Manufacturer: Kemet; CompType: Capacitor; Tolerance_%: 5; TaMin_C: -55; TaMax_C: 125; Cap_Case: 0805; AEC Category: Q200
C117 C123 C127 C132 C145 C220 C227 = C2012X5R1H475K125AB: CAP, CERM, 4.7 µF, 50 V, +/- 10%, X5R, 0805; Manufacturer: TDK; Polarized: N; CompType: Capacitor; Value: 4.7uF; U/M: EA; Cap_F: 0.0000047; Tolerance_%: 10; Value1: Unknown; TaMin_C: -55; TaMax_C: 85; Cap_Case: 0805; AEC Category: Q200
C135 C136 = C0805C105K5RACTU: CAP, CERM, 1 µF, 50 V, +/- 5%, X7R, 0805; Manufacturer: Kemet; CompType: Capacitor; Tolerance_%: 10; TaMin_C: -55; TaMax_C: 125; Cap_Case: 0805; AEC Category: Q200
L3-L5 = MPZ2012S300AT000: Ferrite Bead, 30 ohm @ 100 MHz, 6 A, 0805; Manufacturer: TDK; Imax_A: 6; DCR_ohm: 0.01; Value1: 0.01 ohm; Value2: 6A; ZTyp@100MHz_Ohm: 30
R72 R73 R75 R84 R85 R87 R96 R97 R99 = TNPW12061M00BXTY: RES, 1 M, 0.1%, 0.25 W, 15 PPM / C, AEC-Q200; Manufacturer: Vishay; CompType: Resistor; Tolerance_%: 0.1; VDC_V: 200V; AEC Category: Q200
R74 R83 R86 R95 R98 R107 = CRCW08057K50FKEA: RES, 7.5K, 1%, 0.125 W, 0805; Manufacturer: Vishay-Dale; CompType: Resistor; Value: 348; Tolerance_%: 1; Power_W: 0.125; VDC_V: 150; TempCo: 100 ppm/C; EIA_Code: E96; U/M: EA; AEC Category: Q200
R76 R77 R80 R81 R88 R89 R92 R93 R100 R101 R104 R105 = CRCW08054K70FKEA: RES, 4.7K, 1%, 0.125 W, 0805; Manufacturer: Vishay-Dale; CompType: Resistor; Tolerance_%: 1; Power_W: 0.125; VDC_V: 150; TempCo: 100 ppm/C; EIA_Code: E96; U/M: EA; AEC Category: Q200
R78 R82 R90 R94 R102 R106 = TNPW12062K00BEEA: RES, 2 k,  0.1%, 0.25 W, 25 PPM / C, AEC-Q200; Manufacturer: Vishay; CompType: Resistor; Tolerance_%: 0.1; VDC_V: 200V; AEC Category: Q200
R79 R91 R103 = CRCW080568R1FKEA: RES, 68.1, 1%, 0.125 W, 0805; Manufacturer: Vishay-Dale; CompType: Resistor; Value: 348; Value_Code: 68R1; Tolerance_%: 1; Power_W: 0.125; VDC_V: 150; TempCo: 100 ppm/C; EIA_Code: E96; U/M: EA; AEC Category: Q200
TP_GND TP_VLM = 5012: Test Point, Multipurpose, White, TH; Manufacturer: Keystone; CompType: Test Point Loop; ContactFinish: Silver
TP_VL1 TP_VLI1 = 5011: Test Point, Multipurpose, Black, TH; Manufacturer: Keystone; CompType: Test Point Loop; ContactFinish: Silver
TP_VL2 TP_VLI2 = 5010: Test Point, Multipurpose, Red, TH; Manufacturer: Keystone; CompType: Test Point Loop; ContactFinish: Silver
TP_VL3 TP_VLI3 = 5127: Test Point, Multipurpose, Blue, TH; Manufacturer: Keystone; CompType: Test Point Loop; U/M: EA; ContactFinish: Silver
U19 U23 U25 = AMC1301DWVR: Precision +/-250-mV Input, 3-us Delay, Reinforced Isolated Amplifier, DWV0008A (SOIC-8); Manufacturer: Texas Instruments; SymbolCreator: Altium; SizeArea_mm2: 67.275; SizeAreaWB_mm2: 105.975; SizeX_mm: 11.5; SizeY_mm: 5.85; SizeZ_mm: 2.8; CompType: IC; U/M: EA
U20 U24 U26 = MCP6021T-E/OT: General Purpose Amplifier 1 Circuit Rail-to-Rail SOT-23-5; Manufacturer: Microchip Technology; Number of Channels: 2; Offset Drift(Typ)(uV/C): 1.5; Total Supply Voltage(Max)(+5V is 5, +/-5V is 10): 5.5; Total Supply Voltage(Min)(+5V is 5, +/-5V is 10): 2.5
U21 = REF2033: IC VREF SERIES 1.65V/3.3V 5SOT; PartNumber: REF2033AIDDCR; Manufacturer: Texas Instruments
U22 = DCH010505SN7: Miniature, 1 W, 3 kVDC Isolated DC-DC Converter, -40 to 85 degC, 4-pin Module (EDJ4), Pb-Free (RoHS); Manufacturer: Texas Instruments; Alternate PartNumber: Equivalent; Iout(Max)(A): 0.2; Regulated Outputs(#): 1; SubFamily: 1 W & 2 W Miniature; Vin(Max)(V): 5.5; Vin(Min)(V): 4.5

## Sheet Vienna_PFC_PowerStage.SchDoc
size C; DocumentNumber: 3; SheetNumber: 3; SheetTotal: 11
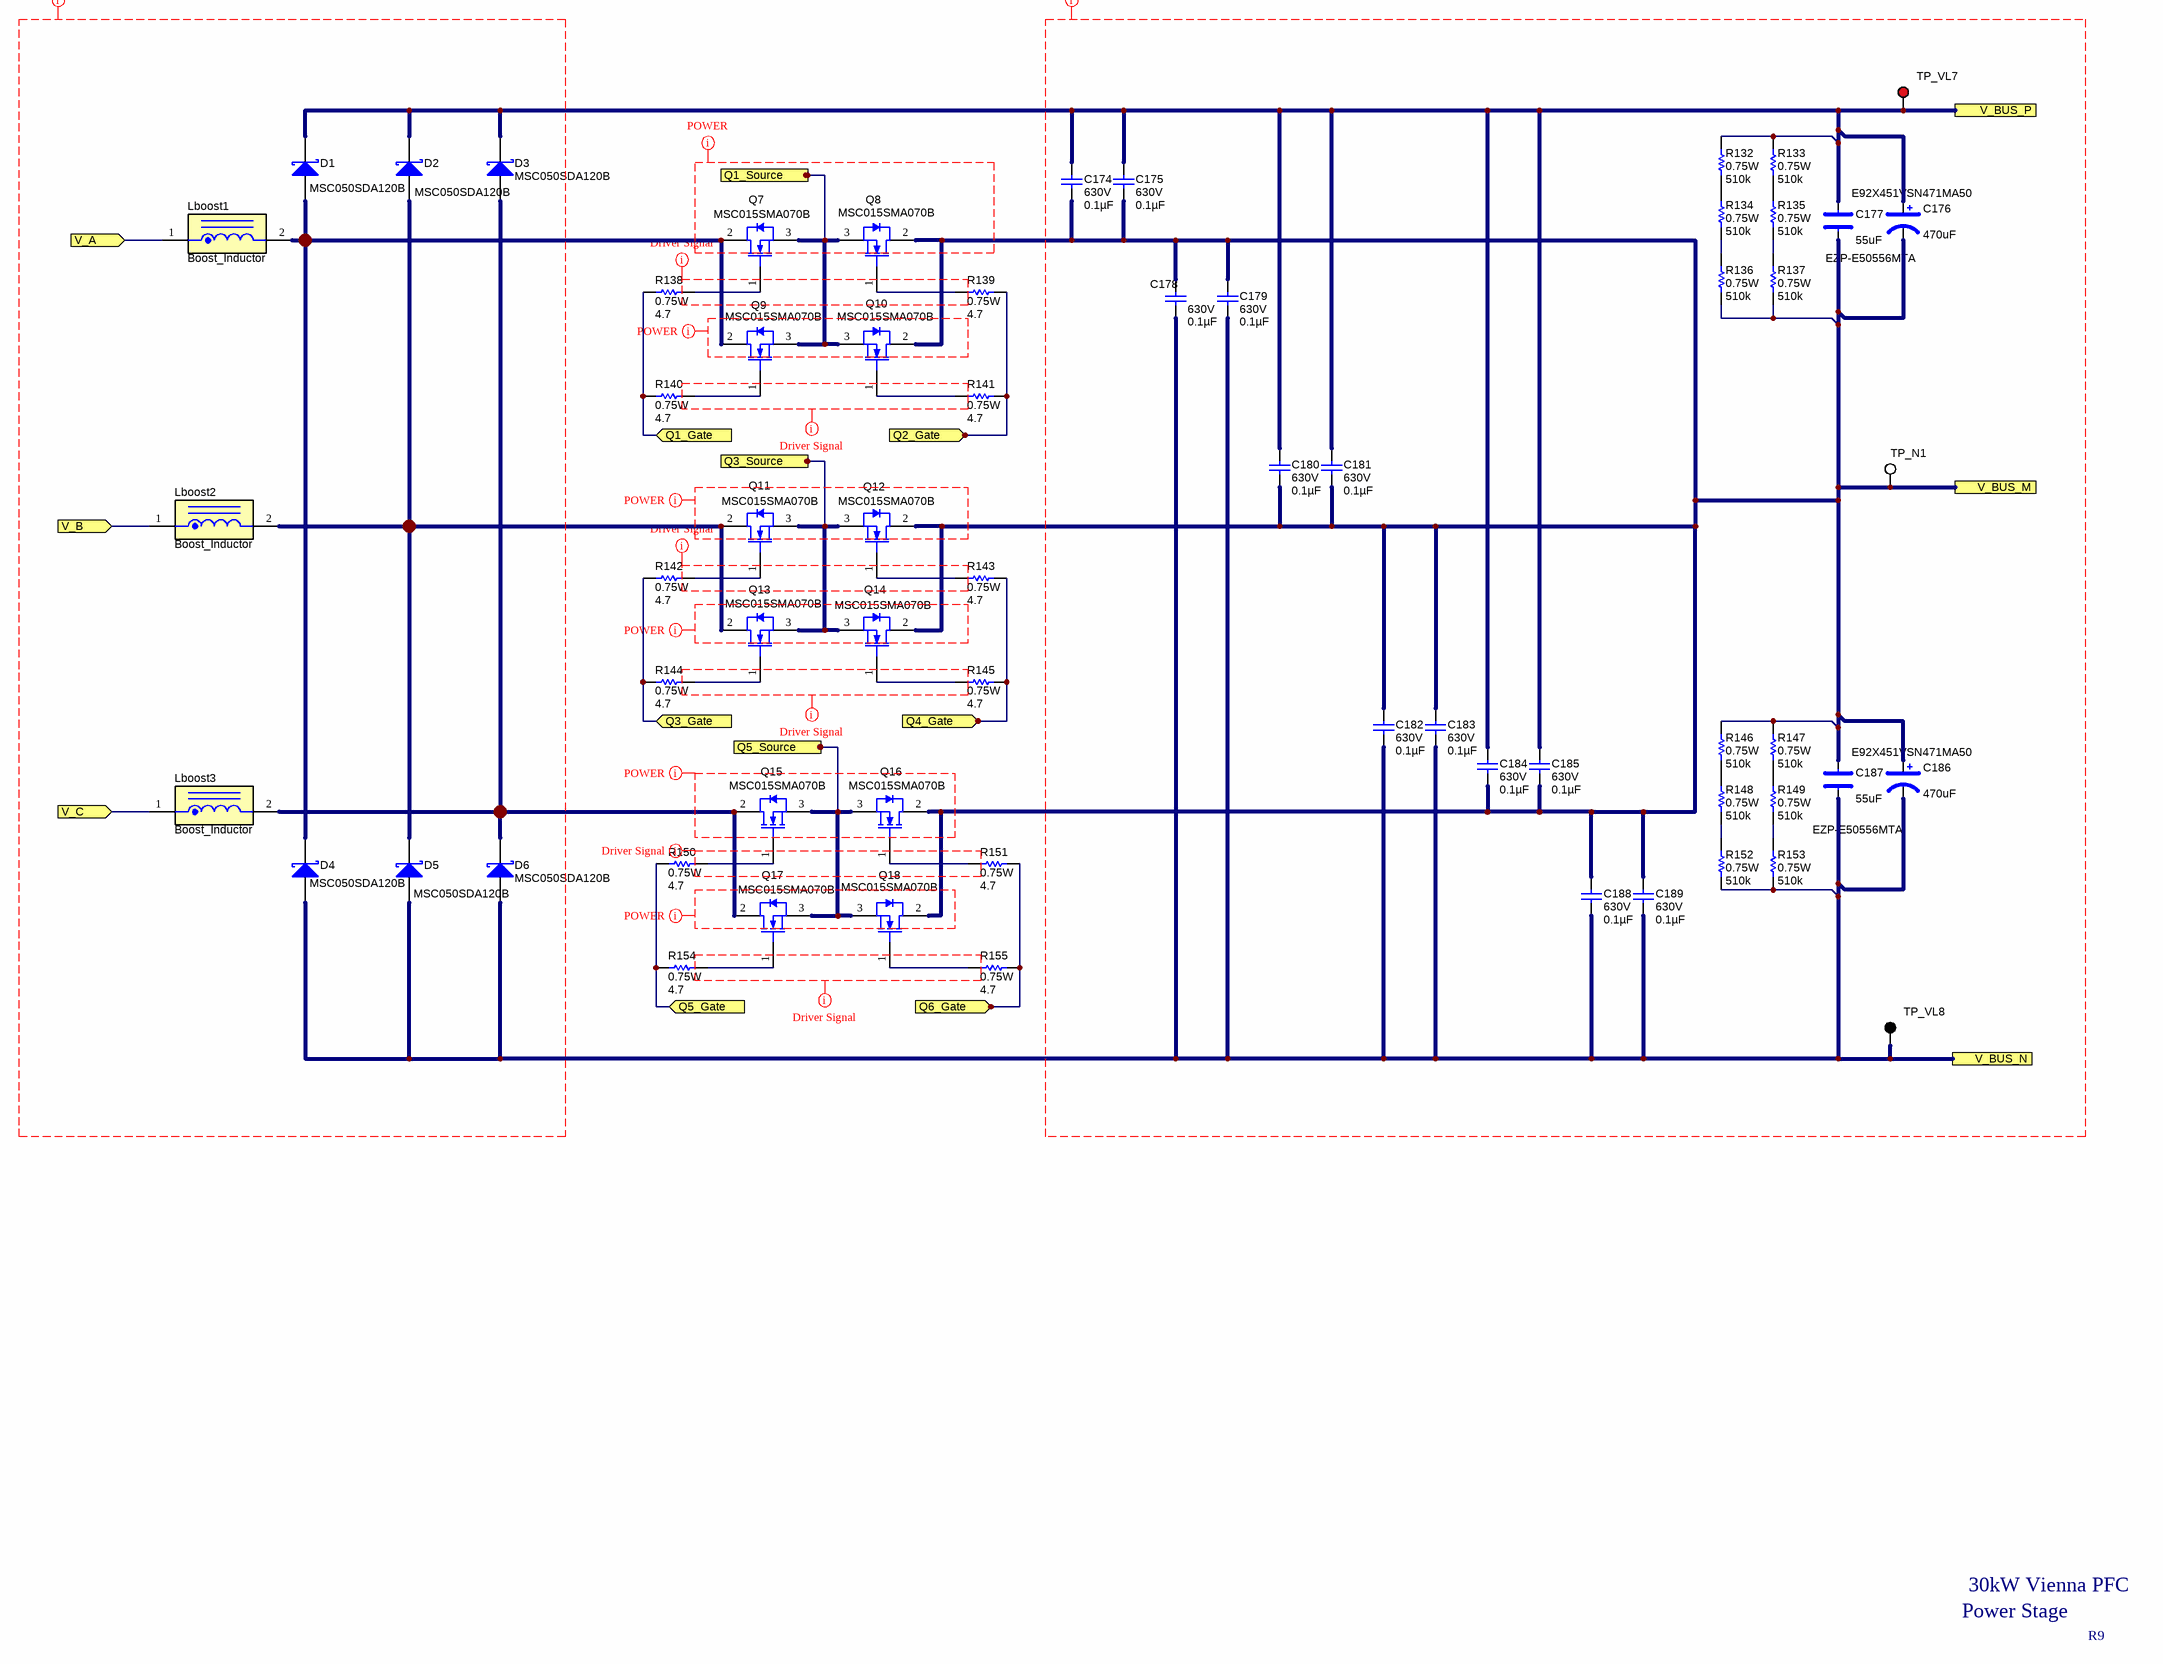
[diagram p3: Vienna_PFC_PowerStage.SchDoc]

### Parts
(Parts that share a designator on the sheet are numbered #1, #2 ... from top to bottom, then left to right.)
?#4  (no value)  (graphical)
C174  VDC_V: 630V  ValueDisplayed: 0.1µF  [1812]  (hidden comment: CKG45KX7R2J104K290JJ)
C175  VDC_V: 630V  ValueDisplayed: 0.1µF  [1812]  (hidden comment: CKG45KX7R2J104K290JJ)
C176  E92X451VSN471MA50  value 470uF  [E92X451VSN471MA50]
C177  EZP-E50556MTA  value 55uF  [EZP-E50556MTA]
C178  VDC_V: 630V  ValueDisplayed: 0.1µF  [1812]  (hidden comment: CKG45KX7R2J104K290JJ)
C179  VDC_V: 630V  ValueDisplayed: 0.1µF  [1812]  (hidden comment: CKG45KX7R2J104K290JJ)
C180  VDC_V: 630V  ValueDisplayed: 0.1µF  [1812]  (hidden comment: CKG45KX7R2J104K290JJ)
C181  VDC_V: 630V  ValueDisplayed: 0.1µF  [1812]  (hidden comment: CKG45KX7R2J104K290JJ)
C182  VDC_V: 630V  ValueDisplayed: 0.1µF  [1812]  (hidden comment: CKG45KX7R2J104K290JJ)
C183  VDC_V: 630V  ValueDisplayed: 0.1µF  [1812]  (hidden comment: CKG45KX7R2J104K290JJ)
C184  VDC_V: 630V  ValueDisplayed: 0.1µF  [1812]  (hidden comment: CKG45KX7R2J104K290JJ)
C185  VDC_V: 630V  ValueDisplayed: 0.1µF  [1812]  (hidden comment: CKG45KX7R2J104K290JJ)
C186  E92X451VSN471MA50  value 470uF  [E92X451VSN471MA50]
C187  EZP-E50556MTA  value 55uF  [EZP-E50556MTA]
C188  VDC_V: 630V  ValueDisplayed: 0.1µF  [1812]  (hidden comment: CKG45KX7R2J104K290JJ)
C189  VDC_V: 630V  ValueDisplayed: 0.1µF  [1812]  (hidden comment: CKG45KX7R2J104K290JJ)
D1  MSC050SDA120B  [TO-247-ress]
D2  MSC050SDA120B  [TO-247-ress]
D3  MSC050SDA120B  [TO-247-ress]
D4  MSC050SDA120B  [TO-247-ress]
D5  MSC050SDA120B  [TO-247-ress]
D6  MSC050SDA120B  [TO-247-ress]
Lboost1  Boost_Inductor  [Boost_Inductor]
Lboost2  Boost_Inductor  [Boost_Inductor]
Lboost3  Boost_Inductor  [Boost_Inductor]
Q7  MSC015SMA070B  [TO-247]
Q8  MSC015SMA070B  [TO-247]
Q9  MSC015SMA070B  [TO-247]
Q10  MSC015SMA070B  [TO-247]
Q11  MSC015SMA070B  [TO-247]
Q12  MSC015SMA070B  [TO-247]
Q13  MSC015SMA070B  [TO-247]
Q14  MSC015SMA070B  [TO-247]
Q15  MSC015SMA070B  [TO-247]
Q16  MSC015SMA070B  [TO-247]
Q17  MSC015SMA070B  [TO-247]
Q18  MSC015SMA070B  [TO-247]
R132  Value2: 0.75W  ValueDisplayed: 510k  [2010]  (hidden comment: CRCW2010510KJNEF)
R133  Value2: 0.75W  ValueDisplayed: 510k  [2010]  (hidden comment: CRCW2010510KJNEF)
R134  Value2: 0.75W  ValueDisplayed: 510k  [2010]  (hidden comment: CRCW2010510KJNEF)
R135  Value2: 0.75W  ValueDisplayed: 510k  [2010]  (hidden comment: CRCW2010510KJNEF)
R136  Value2: 0.75W  ValueDisplayed: 510k  [2010]  (hidden comment: CRCW2010510KJNEF)
R137  Value2: 0.75W  ValueDisplayed: 510k  [2010]  (hidden comment: CRCW2010510KJNEF)
R138  Value2: 0.75W  ValueDisplayed: 4.7  [1206_190]  (hidden comment: CRCW12062R20FKEAHP)
R139  Value2: 0.75W  ValueDisplayed: 4.7  [1206_190]  (hidden comment: CRCW12062R20FKEAHP)
R140  Value2: 0.75W  ValueDisplayed: 4.7  [1206_190]  (hidden comment: CRCW12062R20FKEAHP)
R141  Value2: 0.75W  ValueDisplayed: 4.7  [1206_190]  (hidden comment: CRCW12062R20FKEAHP)
R142  Value2: 0.75W  ValueDisplayed: 4.7  [1206_190]  (hidden comment: CRCW12062R20FKEAHP)
R143  Value2: 0.75W  ValueDisplayed: 4.7  [1206_190]  (hidden comment: CRCW12062R20FKEAHP)
R144  Value2: 0.75W  ValueDisplayed: 4.7  [1206_190]  (hidden comment: CRCW12062R20FKEAHP)
R145  Value2: 0.75W  ValueDisplayed: 4.7  [1206_190]  (hidden comment: CRCW12062R20FKEAHP)
R146  Value2: 0.75W  ValueDisplayed: 510k  [2010]  (hidden comment: CRCW2010510KJNEF)
R147  Value2: 0.75W  ValueDisplayed: 510k  [2010]  (hidden comment: CRCW2010510KJNEF)
R148  Value2: 0.75W  ValueDisplayed: 510k  [2010]  (hidden comment: CRCW2010510KJNEF)
R149  Value2: 0.75W  ValueDisplayed: 510k  [2010]  (hidden comment: CRCW2010510KJNEF)
R150  Value2: 0.75W  ValueDisplayed: 4.7  [1206_190]  (hidden comment: CRCW12062R20FKEAHP)
R151  Value2: 0.75W  ValueDisplayed: 4.7  [1206_190]  (hidden comment: CRCW12062R20FKEAHP)
R152  Value2: 0.75W  ValueDisplayed: 510k  [2010]  (hidden comment: CRCW2010510KJNEF)
R153  Value2: 0.75W  ValueDisplayed: 510k  [2010]  (hidden comment: CRCW2010510KJNEF)
R154  Value2: 0.75W  ValueDisplayed: 4.7  [1206_190]  (hidden comment: CRCW12062R20FKEAHP)
R155  Value2: 0.75W  ValueDisplayed: 4.7  [1206_190]  (hidden comment: CRCW12062R20FKEAHP)
TP_N1  5012  [Keystone5012]  (value not drawn)
TP_VL7  5010  [Keystone5010]  (value not drawn)
TP_VL8  5011  [Keystone5011]  (value not drawn)

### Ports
Q1_Gate (in), Q1_Source (in), Q2_Gate (in), Q3_Gate (in), Q3_Source (in), Q4_Gate (in), Q5_Gate (in), Q5_Source (in), Q6_Gate (in), V_A (in), V_B (in), V_BUS_M, V_BUS_N, V_BUS_P, V_C (in)

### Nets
GND1: Q7.3(S) Q8.3(S) Q9.3(S) Q10.3(S) ; port Q1_Source
GND3: Q11.3(S) Q12.3(S) Q13.3(S) Q14.3(S) ; port Q3_Source
GND5: Q15.3(S) Q16.3(S) Q17.3(S) Q18.3(S) ; port Q5_Source
V_BUS_M: C174.2 C175.2 C176.2 C177.1 C178.1 C179.1 C180.2 C181.2 C182.1 C183.1 C184.2 C185.2 C186.1 C187.2 C188.1 C189.1 Q8.2(D) Q10.2(D) Q12.2(D) Q14.2(D) Q16.2(D) Q18.2(D) R136.1 R137.1 R146.2 R147.2 TP_N1.1 ; port V_BUS_M
VBUSN: C178.2 C179.2 C182.2 C183.2 C186.2 C187.1 C188.2 C189.2 D4.2(A) D5.2(A) D6.2(A) R152.1 R153.1 TP_VL8.1 ; port V_BUS_N
VBUSP: C174.1 C175.1 C176.1 C177.2 C180.1 C181.1 C184.1 C185.1 D1.1(K) D2.1(K) D3.1(K) R132.2 R133.2 TP_VL7.1 ; port V_BUS_P
NetD1_2: D1.2(A) D4.1(K) Lboost1.2 Q7.2(D) Q9.2(D)
NetD2_2: D2.2(A) D5.1(K) Lboost2.2 Q11.2(D) Q13.2(D)
NetD3_2: D3.2(A) D6.1(K) Lboost3.2 Q15.2(D) Q17.2(D)
NetLboost1_1: Lboost1.1 ; port V_A
NetLboost2_1: Lboost2.1 ; port V_B
NetLboost3_1: Lboost3.1 ; port V_C
NetQ7_1: Q7.1(G) R138.2
NetQ8_1: Q8.1(G) R139.1
NetQ9_1: Q9.1(G) R140.2
NetQ10_1: Q10.1(G) R141.1
NetQ11_1: Q11.1(G) R142.2
NetQ12_1: Q12.1(G) R143.1
NetQ13_1: Q13.1(G) R144.2
NetQ14_1: Q14.1(G) R145.1
NetQ15_1: Q15.1(G) R150.2
NetQ16_1: Q16.1(G) R151.1
NetQ17_1: Q17.1(G) R154.2
NetQ18_1: Q18.1(G) R155.1
NetR11_2: R139.2 R141.2 ; port Q2_Gate
NetR12_2: R138.1 R140.1 ; port Q1_Gate
NetR28_2: R143.2 R145.2 ; port Q4_Gate
NetR29_2: R142.1 R144.1 ; port Q3_Gate
NetR44_2: R151.2 R155.2 ; port Q6_Gate
NetR45_2: R150.1 R154.1 ; port Q5_Gate
NetR132_1: R132.1 R134.2
NetR133_1: R133.1 R135.2
NetR134_1: R134.1 R136.2
NetR135_1: R135.1 R137.2
NetR146_1: R146.1 R148.2
NetR147_1: R147.1 R149.2
NetR148_1: R148.1 R152.2
NetR149_1: R149.1 R153.2

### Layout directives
net class POWER: (no net found under the mark)
net class Driver Signal: (no net found under the mark)

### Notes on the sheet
- 30kW Vienna PFC
- Power Stage
- R9

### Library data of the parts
?#4 = Title Block C
C174 C175 C178-C185 C188 C189 = CKG45KX7R2J104K290JJ: CAP, CERM, 0.1 µF, 630V, +/- 10%, X7R, 1206; Value: 33uF; Value1: Unknown; AEC Category: Q200
C176 C186 = E92X451VSN471MA50: Aluminum Electrolytic Capacitors - Snap In 450V 470uF 20% Long Life; Manufacturer: United Chemi-Con (UCC)
C177 C187 = EZP-E50556MTA: CAP FILM 55UF 10% 500VDC RAD 4LD; Manufacturer: Panasonic Electronic Components; CompType: Film Capacitors
D1-D6 = MSC050SDA120B: DIODE SCHOTTKY 1.2KV 50A TO247; Manufacturer: Microsemi Corporation; CompType: Diodes - Rectifiers - Single
Lboost1-Lboost3 = Boost_Inductor: Boost_Inductor, Handmake
Q7-Q18 = MSC015SMA070B: GEN2 SIC MOSFET 700V 15MOHM TO-247-3; Manufacturer: Microsemi Corporation; CompType: Transistors - FETs, MOSFETs - Single
R132-R137 R146-R149 R152 R153 = CRCW2010510KJNEF: RES, 510 k, 5%, 0.75 W, AEC-Q200 Grade 0, 2010; Manufacturer: Vishay-Dale; CompType: Resistor; Value: 510k; Res_ohm: 510000; Tolerance_%: 5; Power_W: 0.75; VDC_V: 400; TempCo: 200 ppm/C; SizeArea_mm2: 12.5; SizeY_mm: 2.5; SizeZ_mm: 1.66; EIA_Code: E24; U/M: EA; AEC Category: Q200; AEC Qualified: Y; AEC Grade: 0
R138-R145 R150 R151 R154 R155 = CRCW12064R70FKEAHP: RES, 4.7, 1%, 0.75 W, 1206; Manufacturer: Vishay-Dale; CompType: Resistor; Value: 4.7; Value_Code: 4R7; Tolerance_%: 1; Power_W: 0.75; VDC_V: 200V; TempCo: 100 ppm/C; U/M: EA; AEC Category: Q200
TP_N1 = 5012: as TP_GND on sheet Vienna_PFC_InputVoltageSensor
TP_VL7 = 5010: as TP_VL2 on sheet Vienna_PFC_InputVoltageSensor
TP_VL8 = 5011: as TP_VL1 on sheet Vienna_PFC_InputVoltageSensor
